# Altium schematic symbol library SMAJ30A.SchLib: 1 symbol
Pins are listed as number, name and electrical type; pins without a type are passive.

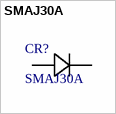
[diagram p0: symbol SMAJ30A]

## SMAJ30A
designator CR?
No Description Available; Manufacturer_Name: Littelfuse Inc
footprint SMASeries_LTF
pins: 1, 2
